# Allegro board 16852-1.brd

Outline 292.8 x 129.5 mm; copper layers: TOP, L2VCC, L3, L4, L5GND, L6, L7GND, BOTTOM. Coordinates in mm from the lower left corner of the outline.

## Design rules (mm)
net group AUDIO_BEEP_15MIL: nets AUD_PORTA_L_HPMIC1 AUD_PORTA_R_HPMIC1
net group CL_CLK: nets CL_CLK CL_CLK_R
net group CL_DATA: nets CL_DATA CL_DATA_R
net group CL_RST#: nets CL_RST# CL_RST#_R
net group CLK_PCIE_WWAN-DIFF1: nets CLK_PCIE_N5_WWAN# CLK_PCIE_P5_WWAN
net group DDPB_CTRL_HDMI-DIFF1: nets CPU_DP1_CTRL_CLK CPU_DP1_CTRL_DATA
net group DDPB_CTRL_HDMI_C-DIFF1: nets DDC_CLK_HDMI DDC_DATA_HDMI
net group DDPC_CTRL_HDMI-DIFF1: nets CPU_DP2_CTRL_CLK CPU_DP2_CTRL_DATA
net group DDR4_A_BA_40-MW: nets M_A_BA0 M_A_BA1
net group DDR4_A_BG_40-MW: nets M_A_BG0 M_A_BG1
net group DDR4_A_ODT10-MW: nets M_A_DIMA_ODT0 M_A_DIMA_ODT1
net group DDR4_B_BA_40-MW: nets M_B_BA0 M_B_BA1
net group DDR4_B_BG_40-MW: nets M_B_BG0 M_B_BG1
net group DDR4_B_ODT10-MW: nets M_B_DIMB_ODT0 M_B_DIMB_ODT1
net group DMIC_DA_CLK-DIFF1: nets DMIC_CLK_R DMIC_DATA_R
net group DMIC_DA_CLK_C-DIFF1: nets DMIC_CLK_EDP DMIC_DATA_EDP
net group DMIC_DA_CLK_R-DIFF1: nets DMIC_CLK DMIC_DATA
net group EDP_AUX_CON_N: nets EDP_AUX_CON_N EDP_AUX_CPU_N
net group EDP_AUX_CON_P: nets EDP_AUX_CON_P EDP_AUX_CPU_P
net group EDP_TX_CON_N0: nets EDP_TX_CON_N0 EDP_TX_CPU_N0
net group EDP_TX_CON_N1: nets EDP_TX_CON_N1 EDP_TX_CPU_N1
net group EDP_TX_CON_P0: nets EDP_TX_CON_P0 EDP_TX_CPU_P0
net group EDP_TX_CON_P1: nets EDP_TX_CON_P1 EDP_TX_CPU_P1
net group GPU_THERMAL-DIFF1: nets GPU_DMINUS GPU_DPLUS
net group HDMI_CLK: nets HDMI_CLK_R HDMI_CLK_R_C
net group HDMI_CLK#: nets HDMI_CLK#_R HDMI_CLK#_R_C
net group HDMI_DATA0: nets HDMI_DATA0_R HDMI_DATA0_R_C
net group HDMI_DATA0#: nets HDMI_DATA0#_R HDMI_DATA0#_R_C
net group HDMI_DATA1: nets HDMI_DATA1_R HDMI_DATA1_R_C
net group HDMI_DATA1#: nets HDMI_DATA1#_R HDMI_DATA1#_R_C
net group HDMI_DATA2: nets HDMI_DATA2_R HDMI_DATA2_R_C
net group HDMI_DATA2#: nets HDMI_DATA2#_R HDMI_DATA2#_R_C
net group I2C0_TCH_PAD-DIFF1: nets I2C0_SCL_TCH_PAD I2C0_SDA_TCH_PAD
net group ICSP-DIFF1: nets ICSP_CLOCK ICSP_DATA
net group ICSP_C-DIFF1: nets ICSP_CLK_R ICSP_DATA_R
net group ISH_I2C0-DIFF1: nets I2C0_SCL I2C0_SDA
net group ISH_I2C1-DIFF1: nets I2C1_SCL I2C1_SDA
net group M_A_CLK0-DIFF1: nets M_A_CLK0 M_A_CLK#0
net group M_A_CLK1-DIFF1: nets M_A_CLK1 M_A_CLK#1
net group M_A_DQS0-DIFF1: nets M_A_DQS_DN0 M_A_DQS_DP0
net group M_A_DQS1-DIFF1: nets M_A_DQS_DN1 M_A_DQS_DP1
net group M_A_DQS2-DIFF1: nets M_A_DQS_DN2 M_A_DQS_DP2
net group M_A_DQS3-DIFF1: nets M_A_DQS_DN3 M_A_DQS_DP3
net group M_A_DQS4-DIFF1: nets M_A_DQS_DN4 M_A_DQS_DP4
net group M_A_DQS5-DIFF1: nets M_A_DQS_DN5 M_A_DQS_DP5
net group M_A_DQS6-DIFF1: nets M_A_DQS_DN6 M_A_DQS_DP6
net group M_A_DQS7-DIFF1: nets M_A_DQS_DN7 M_A_DQS_DP7
net group M_B_CLK0-DIFF186: nets M_B_CLK0 M_B_CLK#0
net group M_B_CLK1-DIFF187: nets M_B_CLK1 M_B_CLK#1
net group M_B_DQS0-DIFF188: nets M_B_DQS_DN0 M_B_DQS_DP0
net group M_B_DQS1-DIFF188: nets M_B_DQS_DN1 M_B_DQS_DP1
net group M_B_DQS2-DIFF188: nets M_B_DQS_DN2 M_B_DQS_DP2
net group M_B_DQS3-DIFF188: nets M_B_DQS_DN3 M_B_DQS_DP3
net group M_B_DQS4-DIFF188: nets M_B_DQS_DN4 M_B_DQS_DP4
net group M_B_DQS5-DIFF188: nets M_B_DQS_DN5 M_B_DQS_DP5
net group M_B_DQS6-DIFF188: nets M_B_DQS_DN6 M_B_DQS_DP6
net group M_B_DQS7-DIFF188: nets M_B_DQS_DN7 M_B_DQS_DP7
net group PBAT_PRES#: nets PBAT_PRES1# PBAT_PRES#
net group PBAT_SMBCLK1: nets PBAT_SMBCLK1 SMBCLK1
net group PBAT_SMBDAT1: nets PBAT_SMBDAT1 SMBDA1
net group PCH_DPC_0-DIFF1: nets PCH_DPC_N0 PCH_DPC_P0
net group PCH_DPC_1-DIFF1: nets PCH_DPC_N1 PCH_DPC_P1
net group PCH_DPC_AUX-DIFF: nets PCH_DPC_AUXN PCH_DPC_AUXP
net group PCI_CLK_LPC0: nets PCI_CLK_LPC0 PCI_CLK_LPC1_B
net group PCIE_CLK_XDP_N: nets PCIE_CLK_XDP_N PEG_CLK_XDP#
net group PCIE_CLK_XDP_P: nets PCIE_CLK_XDP_P PEG_CLK_XDP
net group PCIE_RCOMP-DIFF: nets PCIE_RCOMPN PCIE_RCOMPP
net group PCIE_RX_CON_N5: nets PCIE_RX_CON_N5 PCIE_RX_CPU_N5
net group PCIE_RX_CON_P5: nets PCIE_RX_CON_P5 PCIE_RX_CPU_P5
net group PCIE_RX_CPU6-DIFF192: nets PCIE_RX_CPU_N6 PCIE_RX_CPU_P6
net group PCIE_TX_CON_N5: nets PCIE_TX_CON_N5 PCIE_TX_CPU_N5
net group PCIE_TX_CON_N6: nets PCIE_TX_CON_N6 PCIE_TX_CPU_N6
net group PCIE_TX_CON_P5: nets PCIE_TX_CON_P5 PCIE_TX_CPU_P5
net group PCIE_TX_CON_P6: nets PCIE_TX_CON_P6 PCIE_TX_CPU_P6
net group PEG_CLK_CPU1-DIFF221: nets PEG_CLK1_CPU PEG_CLK1_CPU#
net group PEG_CLK_CPU2-DIFF198: nets PEG_CLK2_CPU PEG_CLK2_CPU#
net group PEG_RX_CPU_N0: nets PEG_RX_CPU_N0 PEG_RX_GPU_N0
net group PEG_RX_CPU_N1: nets PEG_RX_CPU_N1 PEG_RX_GPU_N1
net group PEG_RX_CPU_N2: nets PEG_RX_CPU_N2 PEG_RX_GPU_N2
net group PEG_RX_CPU_N3: nets PEG_RX_CPU_N3 PEG_RX_GPU_N3
net group PEG_RX_CPU_P0: nets PEG_RX_CPU_P0 PEG_RX_GPU_P0
net group PEG_RX_CPU_P1: nets PEG_RX_CPU_P1 PEG_RX_GPU_P1
net group PEG_RX_CPU_P2: nets PEG_RX_CPU_P2 PEG_RX_GPU_P2
net group PEG_RX_CPU_P3: nets PEG_RX_CPU_P3 PEG_RX_GPU_P3
net group PEG_TX_CPU_N0: nets PEG_TX_CPU_N0 PEG_TX_GPU_N0
net group PEG_TX_CPU_N1: nets PEG_TX_CPU_N1 PEG_TX_GPU_N1
net group PEG_TX_CPU_N2: nets PEG_TX_CPU_N2 PEG_TX_GPU_N2
net group PEG_TX_CPU_N3: nets PEG_TX_CPU_N3 PEG_TX_GPU_N3
net group PEG_TX_CPU_P0: nets PEG_TX_CPU_P0 PEG_TX_GPU_P0
net group PEG_TX_CPU_P1: nets PEG_TX_CPU_P1 PEG_TX_GPU_P1
net group PEG_TX_CPU_P2: nets PEG_TX_CPU_P2 PEG_TX_GPU_P2
net group PEG_TX_CPU_P3: nets PEG_TX_CPU_P3 PEG_TX_GPU_P3
net group POWER_240M_POWER: nets 1D5V_VGA_S0 PWR_1D5V
net group POWER_280M_19V: nets PWR_DCBATOUT_1D35V PWR_DCBATOUT_VDDQ
net group PWR_DISB: nets PWR_VCCGT_DISB#_A PWR_VCORE_DISB#
net group PWR_V_F: nets DCBATOUT_VCCGT DCBATOUT_VCORE
net group PWR_VCCGT: nets PWR_VCCGT_CSCOMP PWR_VCCGT_ILIM_R
net group PWR_VCORE_VSN: nets PWR_VCORE_VSN PWR_VCORE_VSN_R
net group SENSE_CHG_AC-DIFF: nets PWR_CHG_ACN PWR_CHG_ACP
net group SENSE_CHG_SR-DIFF: nets PWR_CHG_SRN PWR_CHG_SRP
net group SIGNAL_V_F_8_OHM-MW: nets CFG3 XDP_DBRESET#
net group SIGNAL_V_F_18_OHM-MW: nets H_PECI PECI_EC
net group SMBUS0_PCH-DIFF1: nets SML0_SMBCLK SML0_SMBDATA
net group SMBUS1_GPU-DIFF1: nets SMB_CLK_VGA SMB_DATA_VGA
net group SMBUS1_GPU_T8-DIFF1: nets SMB_CLK_VGA_GPUT8 SMB_DATA_VGA_GPUT8
net group SMBUS_XDP-DIFF1: nets XDP_SMBCLK XDP_SMBDAT
net group SPI_WP_CPU: nets SPI_WP_ROM SPI_WP_ROM_R
net group THERM_7718E-DIFF1: nets NCT7718_DXN NCT7718_DXP
net group USB3_PRX_CTX_C1-DIFF1: nets USB3_PRX_CTX_N1_C USB3_PRX_CTX_P1_C
net group USB3_PRX_CTX_C3-DIFF1: nets USB3_PRX_CTX_N3_C USB3_PRX_CTX_P3_C
net group USB3_PTX_CRX_C1-DIFF1: nets USB3_PTX_CRX_N1_C USB3_PTX_CRX_P1_C
net group USB3_PTX_CRX_C2-DIFF1: nets USB3_TXN3_R USB3_TXP3_R
net group USB3_PTX_CRX_C3-DIFF1: nets USB3_PTX_CRX_N3_C USB3_PTX_CRX_P3_C
net group USB3_PTX_CRX_R3-DIFF1: nets USB3_PTX_CRX_N3_R USB3_PTX_CRX_P3_R
net group USB30_RX_CPU1-DIFF1: nets USB30_RX_CPU_N1 USB30_RX_CPU_P1
net group USB30_RX_CPU3-DIFF1: nets USB30_RX_CPU_N3 USB30_RX_CPU_P3
net group USB30_TX_CPU2-DIFF1: nets USB30_TX_CPU_N2 USB30_TX_CPU_P2
net group USB30_TX_CPU3-DIFF1: nets USB30_TX_CPU_N3 USB30_TX_CPU_P3
net group USB_CON6-DIFF6: nets USB_CON_PN6 USB_CON_PP6
net group USB_CPU3-DIFF3: nets USB_CPU_PN3 USB_CPU_PP3
net group USB_CPU6-DIFF6: nets USB_CPU_PN6 USB_CPU_PP6
net group USB_CPU7-DIFF7: nets USB_CPU_PN7 USB_CPU_PP7
net group USB_CPU_PN0: nets USB_PN0_C USB_PN0_R
net group USB_CPU_PN2: nets USB_CPU_PN2 USB_PN2_C
net group USB_CPU_PN5: nets USB_CPU_PN5 USB_PN5_C
net group USB_CPU_PP0: nets USB_PP0_C USB_PP0_R
net group USB_CPU_PP2: nets USB_CPU_PP2 USB_PP2_C
net group USB_CPU_PP5: nets USB_CPU_PP5 USB_PP5_C
net group USB_PN3_PP3_C-DIFF1: nets USB_PN3_C USB_PP3_C
net group USB_WLAN-DIFF219: nets USB_CON_PN7 USB_CON_PP7
net group VRAM_CLK0-DIFF1: nets CLKA0 CLKA0#
net group VRAM_CLK1-DIFF1: nets CLKA1 CLKA1#
net group VRAM_CSA: nets CSA0#_0 CSA1#_0
net group VRAM_QS0-DIFF1: nets QSAN_0 QSAP_0
net group VRAM_QS1-DIFF1: nets QSAN_1 QSAP_1
net group VRAM_QS2-DIFF1: nets QSAN_2 QSAP_2
net group VRAM_QS3-DIFF1: nets QSAN_3 QSAP_3
net group VRAM_QS4-DIFF1: nets QSAN_4 QSAP_4
net group VRAM_QS5-DIFF1: nets QSAN_5 QSAP_5
net group VRAM_QS6-DIFF1: nets QSAN_6 QSAP_6
net group VRAM_QS7-DIFF1: nets QSAN_7 QSAP_7
net group XTAL24_IN: nets XTAL24_IN XTAL24_IN_R
net group AUDIO_12MIL: nets AUD_VREF CBP CPVDD CPVEE LDO1_CAP LDO2_CAP V3D3_STB
net group AUDIO_BEEP1_40MIL: nets AUD_SPK_L+ AUD_SPK_L+_C AUD_SPK_L- AUD_SPK_L-_C AUD_SPK_R+ AUD_SPK_R+_C AUD_SPK_R- AUD_SPK_R-_C
net group AUDIO_BEEP_10MIL: nets AUD_HP1_JACK_L AUD_HP1_JACK_L1 AUD_HP1_JACK_R AUD_HP1_JACK_R1 AUD_PC_BEEP_3246 AUD_PC_BEEP_C AUD_PC_BEEP_R AUD_SENSE AUD_SENSE_A BEEP CBN HDA_SPKR_R JACK_PLUG JACK_PLUG_DET KBC_BEEP_R LINE1-L_C LINE1-L_R LINE1_L LINE1_R LINE1_VREFO_L LINE1_VREFO_R MIC2_VREFO SPKR
net group AUDIO_DIGITAL_50-MW: nets HDA_RST#
net group AUDIO_SLEEVE_40MIL: nets RING2 RING2_HPMIC1 SLEEVE SLEEVE_HPMIC1
net group CFG_50-MW: nets CFG0 CFG1 CFG2 CFG4 CFG5 CFG6 CFG7 CFG8 CFG9 CFG10 CFG11 CFG12 CFG13 CFG14 CFG15 CFG16 CFG17 CFG18 CFG19
net group CLK_50-MW: nets CLK_PCI_LPC CLK_PCI_LPC_MEC CLK_PCI_LPC_R CLKTESTA CLKTESTA_C CLKTESTB CLKTESTB_C PWR_CHG_PROCHOT# SUS_CLK SUS_CLK_WLAN_WWAN SUSCLK_NGFF_C SUSCLK_R SUSCLK_WLAN WLAN_CLKREQ_WLAN#
net group CLK_ITE8010: nets CLK_ITE8010 SMB_CLK_VGA_R SMBCLK2 SML1_SMBCLK THM_SML1_CLK
net group COMP_20MIL: nets CFG_RCOMP CPU_POPIRCOMP CSI2_COMP EDP_COMP EDRAM_OPIO_RCOMP EMMC_RCOMP EOPIO_RCOMP PCH_POPIRCOMP SD_RCOMP USBCOMP XCLK_BIASREF
net group CPU_50-MW: nets CMP_VOUT1 H_PROCHOT# H_PROCHOT#_EC H_PROCHOT#_R H_PROCHOT#_R_R PQ4405_3
net group CPU_50_12MIL: nets H_VCCST_PWRGD H_VCCST_PWRGD_R PCH_THERMTRIP
net group DAT_ITE8010: nets DAT_ITE8010 SMB_DATA_VGA_R SMBDA2 SML1_SMBDATA THM_SML1_DATA
net group DDR4_A_CKE_40-MW: nets M_A_CKE0 M_A_CKE1 M_A_CS#0 M_A_CS#1
net group DDR4_A_CMD_40-MW: nets M_A_A0 M_A_A1 M_A_A2 M_A_A3 M_A_A4 M_A_A5 M_A_A6 M_A_A7 M_A_A8 M_A_A9 M_A_A10 M_A_A11 M_A_A12 M_A_A13 M_A_A14 M_A_A15 M_A_A16 M_A_ACT_N M_A_ALERT_N M_A_PARITY M_B_ALERT_N
net group DDR4_A_DATA_00_50-MW: nets M_A_DQ0 M_A_DQ1 M_A_DQ2 M_A_DQ3 M_A_DQ4 M_A_DQ5 M_A_DQ6 M_A_DQ7
net group DDR4_A_DATA_01_50-MW: nets M_A_DQ8 M_A_DQ9 M_A_DQ10 M_A_DQ11 M_A_DQ12 M_A_DQ13 M_A_DQ14 M_A_DQ15
net group DDR4_A_DATA_02_50-MW: nets M_A_DQ16 M_A_DQ17 M_A_DQ18 M_A_DQ19 M_A_DQ20 M_A_DQ21 M_A_DQ22 M_A_DQ23
net group DDR4_A_DATA_03_50-MW: nets M_A_DQ24 M_A_DQ25 M_A_DQ26 M_A_DQ27 M_A_DQ28 M_A_DQ29 M_A_DQ30 M_A_DQ31
net group DDR4_A_DATA_04_50-MW: nets M_A_DQ32 M_A_DQ33 M_A_DQ34 M_A_DQ35 M_A_DQ36 M_A_DQ37 M_A_DQ38 M_A_DQ39
net group DDR4_A_DATA_05_50-MW: nets M_A_DQ40 M_A_DQ41 M_A_DQ42 M_A_DQ43 M_A_DQ44 M_A_DQ45 M_A_DQ46 M_A_DQ47
net group DDR4_A_DATA_06_50-MW: nets M_A_DQ48 M_A_DQ49 M_A_DQ50 M_A_DQ51 M_A_DQ52 M_A_DQ53 M_A_DQ54 M_A_DQ55
net group DDR4_A_DATA_07_50-MW: nets M_A_DQ56 M_A_DQ57 M_A_DQ58 M_A_DQ59 M_A_DQ60 M_A_DQ61 M_A_DQ62 M_A_DQ63
net group DDR4_B_CKE_40-MW: nets M_B_CKE0 M_B_CKE1 M_B_CS#0 M_B_CS#1
net group DDR4_B_CMD_40-MW: nets M_B_A0 M_B_A1 M_B_A2 M_B_A3 M_B_A4 M_B_A5 M_B_A6 M_B_A7 M_B_A8 M_B_A9 M_B_A10 M_B_A11 M_B_A12 M_B_A13 M_B_A14 M_B_A15 M_B_A16 M_B_ACT_N M_B_PARITY
net group DDR4_B_DATA_00_50-MW: nets M_B_DQ0 M_B_DQ1 M_B_DQ2 M_B_DQ3 M_B_DQ4 M_B_DQ5 M_B_DQ6 M_B_DQ7
net group DDR4_B_DATA_01_50-MW: nets M_B_DQ8 M_B_DQ9 M_B_DQ10 M_B_DQ11 M_B_DQ12 M_B_DQ13 M_B_DQ14 M_B_DQ15
net group DDR4_B_DATA_02_50-MW: nets M_B_DQ16 M_B_DQ17 M_B_DQ18 M_B_DQ19 M_B_DQ20 M_B_DQ21 M_B_DQ22 M_B_DQ23
net group DDR4_B_DATA_03_50-MW: nets M_B_DQ24 M_B_DQ25 M_B_DQ26 M_B_DQ27 M_B_DQ28 M_B_DQ29 M_B_DQ30 M_B_DQ31
net group DDR4_B_DATA_04_50-MW: nets M_B_DQ32 M_B_DQ33 M_B_DQ34 M_B_DQ35 M_B_DQ36 M_B_DQ37 M_B_DQ38 M_B_DQ39
net group DDR4_B_DATA_05_50-MW: nets M_B_DQ40 M_B_DQ41 M_B_DQ42 M_B_DQ43 M_B_DQ44 M_B_DQ45 M_B_DQ46 M_B_DQ47
net group DDR4_B_DATA_06_50-MW: nets M_B_DQ48 M_B_DQ49 M_B_DQ50 M_B_DQ51 M_B_DQ52 M_B_DQ53 M_B_DQ54 M_B_DQ55
net group DDR4_B_DATA_07_50-MW: nets M_B_DQ56 M_B_DQ57 M_B_DQ58 M_B_DQ59 M_B_DQ60 M_B_DQ61 M_B_DQ62 M_B_DQ63
net group DDR4_VREF_40: nets M_VREF_CA_DIMMA M_VREF_CA_DIMMB V_SM_VREF_CNTA V_SM_VREF_CNTB
net group EC_SPI_CLK: nets EC_SPI_CLK SPI1_CLK_ROM_R SPI_CLK_CPU SPI_CLK_ROM SPI_CLK_ROM_R SPI_CLK_ROM_TPM1 SPI_CLK_ROM_TPM2
net group EC_SPI_CS0#: nets EC_SPI_CS0# SPI_CS_CPU_N0 SPI_CS_ROM_N0
net group EC_SPI_MISO: nets EC_SPI_MISO SPI1_SO_ROM_R SPI_SO_CPU SPI_SO_ROM SPI_SO_ROM_R SPI_SO_ROM_TPM1 SPI_SO_ROM_TPM2
net group EC_SPI_MOSI: nets EC_SPI_MOSI SPI1_SI_ROM_R SPI_SI_CPU SPI_SI_ROM SPI_SI_ROM_R SPI_SI_ROM_TPM1 SPI_SI_ROM_TPM2
net group FAN_TACH: nets FAN1_TACH FAN_TACH1 FAN_TACH1_C
net group FBA_VREF: nets FBA_VREF_0 FBA_VREF_1 MVREFDA MVREFSA
net group GND: nets 81208_AGND CHG_AGND EC_AGND JGND MIC_GND
net group H_CPU_SVIDALRT#: nets H_CPU_SVIDALRT# PWR_VCORE_ALERT# VR_SVID_ALERT#
net group H_CPU_SVIDCLK: nets H_CPU_SVIDCLK PWR_VCORE_SCLK VR_SVID_CLK
net group H_CPU_SVIDDAT: nets H_CPU_SVIDDAT PWR_VCORE_SDIO VR_SVID_DATA
net group HDA_BITCLK: nets HDA_BITCLK_CODEC_R
net group HDA_CODEC_SDIN0: nets HDA_SDIN0
net group HDA_CODEC_SDOUT: nets HDA_SDOUT_CODEC_R
net group JTAG-MW: nets PCH_JTAG_TCK PCH_JTAG_TDI PCH_JTAG_TDO PCH_JTAG_TMS
net group KBC: nets KSI0 KSI1 KSI2 KSI3 KSI4 KSI5 KSI6 KSI7 KSO0 KSO1 KSO2 KSO3 KSO4 KSO5 KSO6 KSO7 KSO8 KSO9 KSO10 KSO11 KSO12 KSO13 KSO14 KSO15 KSO16
net group LCD_BKLT: nets BKLT_CTRL EDP_BKLT_CTRL L_BKLT_CTRL LCD_BRIGHTNESS MASK_BASE_LEDS#
net group LED: nets BAT1_LED# BAT2_LED# BATT_WHITE_LED# BATT_WHITE_LED#_M BATT_WHITE_LED_R# CAP_LED# CAP_LED#_S CAP_LED_R# CHG_AMBER_LED# CHG_AMBER_LED#_M CHG_AMBER_LED_R# NGFF_WAKE# PWR_LED# PWR_LED#_B PWR_LED#_S SATA#/BATT_LED_MUXCTL SATA_LED#_R
net group LED_20MIL: nets AMBER_LED_BAT BAT_AMBER BAT_WHITE CAP_LED CAP_LED_Q PWR_LED PWR_LED#_R WHITE_LED_BAT
net group LPC-MW: nets CLKRUN#_R L_CPM_CLK L_CPM_CLK_R LPC_FRAME#_DEBUG LPC_LAD0 LPC_LAD0_C LPC_LAD0_CPM LPC_LAD0_R LPC_LAD1 LPC_LAD1_C LPC_LAD1_CPM LPC_LAD1_R LPC_LAD2 LPC_LAD2_C LPC_LAD2_CPM LPC_LAD2_R LPC_LAD3 LPC_LAD3_C LPC_LAD3_CPM LPC_LAD3_R LPC_LFRAME# LPC_LFRAME#_CPM LPC_LFRAME#_R PCI_CLK_LPC1 PCI_CLK_LPC1_B_R SERIRQ
net group OTHER_4MIL: nets 3.3V_ALW_1 3.3V_RUN_VGA_1 +3VLP A5_TP A67_TP A70_TP A_A0 A_A1 A_A2 AC_DIS AC_IN_KBC# AC_PRESENT AD_IA ATI_RST# AUX_EN_WOWL AUX_EN_WOWL_GP0 AUX_EN_WOWL_R AV1_TP AV71_TP B71_TP BA1_TP BA2_TP BA71_TP BB67_TP BB70_TP BLON_OUT_C BLUETOOTH_EN BLUETOOTH_EN_NGFF BOARD_ID BOARD_ID2 CLKREQ_PCIE#1 CLKREQ_PCIE#2 CLKREQ_PCIE#3 CLKREQ_PCIE#4 CLKREQ_PCIE#5 CLKREQ_PEG#0 CLKRUN# CPU_DP1_HPD CPU_DP2_HPD CPU_DP2_HPD1 DBC_EN_R DBC_PANEL_EN DDPD_CTRLDATA DRAM_RST DRAM_RST_R DRAM_RST_VGA1 DVSS E51_RX1 E51_RX2 E51_TX1 E51_TXD_R E71_TP EC_MUTE# EC_WAKE# EDP_DISP_UTIL EDP_HPD EDP_HPD_CONN FALL_INT2 FFS_INT2 FFS_INT2_Q GPD2/LAN_WAKE# GPIO16_VGA GPIO_8_ROMSO GPIO_9_ROMSI GPIO_10_ROMSCK GPIO_17_THERMAL_INT GPIO_19_CTF GPIO_22_ROMCS# GPP_B2/VRALERT# GPP_B4/CPU_GP3 GPP_B18/GSPI0_MOSI GPP_B23/SML1ALERT# GPP_C2/SMBALERT# GPP_C5/SML0ALERT# GPP_D4/FLASHTRIG GPP_E0/SATAXPCIE0/SATAGP0 GPP_E2/SATAXPCIE2/SATAGP2 GPP_E3/CPU_GP0 GPU_ALERT# GPU_DPRSLP GPU_DPRSLP_R H_CATERR# H_VID3 H_VID4 HDD_DEVSLP_R HDD_DEW1 HDD_DEW2 HDD_FALL_INT HDMI_HPD_B HDMI_HPD_E HOST_DEBUG_TX HPD_HDMI_CON I_ADP I_SYS ICSP_CLR ICSP_CLR_R ILIM_HI ILIM_SEL INT#_ITE8010 INT_TP# IR_CAMERA_DET# IR_CAMERA_DET#_R JDREF JET_SVC JET_SVD JTAG_TCK_VGA JTAG_TDI_VGA JTAG_TDO_VGA JTAG_TMS_VGA JTAG_TRST#_VGA KB_LED_BL_DET KB_LED_DET_C KBC_PWRBTN# L_BKLT_EN L_BKLT_EN_EC LAN_DISABLE# LCD_TST LCD_TST_C LCD_VCC_TEST_EN LCDVDD_EN LED0 LED1 LED2 LID_CL_SIO# ME_FWP_CPU ME_FWP_EC MEM_CALRP0 MESO_SVC MESO_SVD MESO_SVT MESO_U1 MESO_U3 MESW1_B MLPS_EN# MODEL_ID MSM# NC#AA3 NC_R NC_VSYNC NCT7718_ALERT# NGFF_CONFIG_0 NGFF_CONFIG_1 NGFF_CONFIG_2 NGFF_CONFIG_3 NGFF_DEVSLP1 NGFF_MSATA_DEVSLP NGFF_PCIE#_SATA P_SYS PANEL_BKEN_EC PANEL_SIZE_ID PANEL_SIZE_ID_CONN PCH_ALW_ON PCH_BATLOW# PCH_PLTRST#_EC PCH_WAKE# PD4403_A PD4403_K PD# PIRQA# PLL_ANALOG_IN PLT_RST_NGFF# POWER_SW_IN# PQ4405_2 PQ4405_5 PQ4405_6 PQ4408_C PQ4408_E PROC_SELECT# PROJECT_ID2 PS_0 PS_1 PS_2 PS_3 PS_ID_R1 PSYS PWR_CHG_ACOK PWRGOOD_TEST PX_EN Q4009_G RESET_OUT# RTC_DET# SA0_CHA_DIM0 SA0_CHB_DIM0 SA1_CHA_DIM0 SA1_CHB_DIM0 SA2_CHA_DIM0 SA2_CHB_DIM0 SATA_DE1_HDD SATA_DE2_HDD SATA_EQ1_HDD SATA_EQ2_HDD SERIRQ_TPM SIO_EXT_SCI#_R SIO_EXT_SMI# SIO_EXT_SMI#_R SIO_EXT_WAKE# SIO_PWRBTN# SIO_SLP_A# SIO_SLP_S5# SIO_SLP_SUS# SKTOCC# SM_INTRUDER# SPI_IRQ# TESTEN TOUCHPAD_INTR# TP_PMODE_XDP_RST_R_N TP_RESET TP_RS USB_OC1# USB_OC2# USB_UART_SEL_D9 VCC_OPC_1P8_H63 VCI_IN1# VGA_RST# VR_RDY VRAM_ID1 VSS_MECH1 VSS_MECH2 VSS_MECH3 VSSRHA WIFI_RF_EN WLAN_DISABLE#1 XO_IN2 ZVM#
net group PERN0/SATA_B-: nets SATA_RN1/PERN6_L0
net group PERP0/SATA_B+: nets SATA_RP1/PERP6_L0
net group PETN0/SATA_A-: nets SATA_TN1/PETN6_L0
net group PETP0/SATA_A+: nets SATA_TP1/PETP6_L0
net group PLATFORM: nets 0D95V_VGA_EN 0D95V_VGA_EN_R 0D95V_VGA_S0_PG 1D0V_S5_PWRGD 1D8V_EN# 1D8V_EN_R# 1D8V_S5_PWROK 1D8V_VGA_EN 1D8V_VGA_EN# 1D8V_VGA_EN_R# 3.3V_WLAN_EN 3.3V_WLAN_ENABLE 3.3V_WLAN_ENABLE# 3.3V_WWAN_ENABLE 3.3V_WWAN_ENABLE# 3V5V_S0_ON 3V_5V_POK 3V_5V_POK# 3V_5V_POK_C ALWON BLON_OUT CLK_LAN_REQ4#_R CLKA0_CLKA0# CLKA1_CLKA1# DGPU_PWROK_KBC DS3_PWRCTL DSW1 EDP_VDD_EN EXT_PWR_GATE# FIVR_EN_R GPD11/LANPHYPC GPIO_5_AC_BATT H_CPUPWRGD HDD_DET# HW_GPS_DISABLE2# HW_GPS_DISABLE2#_D KBC_PWRBTN#_C LAN_EN LAN_ENABLE_R_C LAN_RSET LCD_MIC_CBL_DET# LCD_MIC_CBL_DET#_R LOM_CABLE_DETECT# MCARD_WWAN_PWREN ME_SUS_PWR_ACK ME_SUS_PWR_ACK_R PCH_DPWROK PCH_PLTRST# PCH_RSMRST# PCIE_CALR_RX PCIE_CALR_TX PCIE_LAN_WAKE# PCIE_WAKE# PCIE_WLAN_WAKE# PCIE_WLAN_WAKE#_R PLT_RST#_DEBUG PLT_RST#_LAN PM_LAN_ENABLE PM_LAN_ENABLE_C PM_PCH_PWROK PM_RSMRST# PM_RSMRST#_M PM_RSMRST#_R PM_RSMRST_PWRGD_XDP PS_S3CNTRL PTP_DIS# PTP_INT#_EC PWR_1D0V_EN PWR_1D0V_PG PWR_1D8V_EN PWR_1D8V_POK PWR_1D35V_EN PWR_1D35V_PG PWR_2D5V_PG PWR_3D3V_EN PWR_VCORE_EN Q502_G Q9102.G RSMRST_PWRGD# RTC_RST# RTCRST_ON RUNPWROK SD_READ_MODE# SIO_SLP_S4# SLP_LAN# SM_DRAMRST# SM_PGCNTL SM_PGCNTL_R SRTC_RST# SUS_STAT#/LPCPD# SUSACK# SUSACK#_R TP_EN# TP_LOCK# TP_ON#_GATE TPM_GPIO0 TPM_GPIO2 TPM_GPIO4 TS#_DIMM0_1 TS#_DIMM1_1 UIM_DET UIM_DET# UIM_DET#_G UIM_DET_D UIM_RESET UIM_RESET_R USB2_ID USB2_VBUSSENSE USB_CHG_EN USB_EN# USB_PWR_EN# USBCHARGER_CB0 VCCSTG_EN VCCSTG_EN_R VCCSTU_EN VCCSTU_EN_R VPP_EN_R WWAN_PERST# WWAN_PWR_EN_D WWAN_PWR_OFF# WWAN_RADIO_DIS# WWAN_RADIO_DIS#_D WWAN_RESET# XO_IN
net group POWER_10M: nets 1.8V_RUN_FB 3V5V_CT1 3V5V_CT2 +V1.00A_XDP +V1.00U_CPU +VCCAMPHYPLL_1P0 +VCCAMPHYPLL_1P0_L +VCCAPLL_1P0 +VCCDSW_1P0 +VCCFUSEPRG +VCCPAZIO +VCCPDSW_3P3 +VCCPRTC_3P3 +VCCST_CPU +VCCSTG +VDDQ_CPU_CLK ACAV_IN ACOK_IN BOOST_MON FAN1_DAC FAN1_DAC_1 FBA_ZQ0 FBA_ZQ1 FBA_ZQ2 FBA_ZQ3 FP_PWR I_BATT LDO3_CAP MIC_CAP PWR_1D0V_PFM PWR_1D0V_SS PWR_1D0V_TON PWR_1D0V_VFB PWR_1D0V_VFB_A PWR_1D35V_FB PWR_1D35V_FB_A PWR_1D35V_ILMT PWR_3D3V_FB PWR_5V_EN PWR_5V_FB PWR_5V_FB_A PWR_CHG_1 PWR_CHG_BATPRES# PWR_CHG_BATSRC PWR_CHG_STAT# PWR_VCCGT_COMP PWR_VCCGT_COMP_R PWR_VCCGT_CSNA PWR_VCCGT_CSP1 PWR_VCCGT_CSP2 PWR_VCCGT_CSPA PWR_VCCGT_CSREF PWR_VCCGT_CSSUM PWR_VCCGT_DIFFOUT PWR_VCCGT_FB PWR_VCCGT_FB_R PWR_VCCGT_ICCMAX PWR_VCCGT_ILIM PWR_VCCGT_IOUT PWR_VCCGT_NTC PWR_VCCGT_PWMA PWR_VCCGT_TSENSE PWR_VCCGT_VCCA PWR_VCCGT_VSN PWR_VCCGT_VSN_R PWR_VCCGT_VSP PWR_VCCSA_COMP PWR_VCCSA_COMP_R PWR_VCCSA_CSN PWR_VCCSA_CSN_NTC PWR_VCCSA_CSP PWR_VCCSA_CSP1B PWR_VCCSA_ICCMAX PWR_VCCSA_ILIM PWR_VCCSA_IOUT PWR_VCCSA_VSN PWR_VCCSA_VSN_R PWR_VCCSA_VSP PWR_VCCSA_VSP_R PWR_VCCSA_VSP_RC PWR_VCORE_COMP PWR_VCORE_COMP_R PWR_VCORE_CSN PWR_VCORE_CSNNTC PWR_VCORE_CSP PWR_VCORE_CSP_1A PWR_VCORE_DRVON PWR_VCORE_ICCMAX PWR_VCORE_ILIM PWR_VCORE_IOUT PWR_VCORE_NTC PWR_VCORE_ROSC_COREGT PWR_VCORE_ROSC_SAUS PWR_VCORE_TSENSE PWR_VCORE_VCC_R PWR_VCORE_VR_RDY PWR_VCORE_VRHOT# PWR_VCORE_VRMP PWR_VCORE_VSP PWR_VCORE_VSP_R PWR_VCORE_VSP_RC PWR_VDDQ_EN PWR_VDDQ_FB PWR_VDDQ_VCC Q6204_G V0.85A_VID0 VCCRTCEXT
net group POWER_10M_POWER: nets AC_IN#_G AD+_G_1 AD+_G_2 AD_OFF_L AD_OFF_R BT+_1 DC_IN_D DDR_VREF_S3 DPLL_PVDD DPLL_VDDC EN/DEM_VGA MPV18 PQ3809_D PQ8206_3 PU8201_36 PU8201_39 PWR_0D6V_S3EN PWR_0D6V_S5EN PWR_0D95V_FB PWR_1D35V_VCC PWR_3D3V_CS PWR_3D3V_VREG PWR_5V_CS PWR_CHG_ACDET PWR_CHG_CMPIN PWR_CHG_CMPOUT PWR_CHG_IADP PWR_CHG_IDCHG PWR_CHG_ILIM PWR_CHG_PMON PWR_CHG_REGN PWR_CHG_SCL PWR_CHG_SDA PWR_CHG_SRN_1 PWR_CHG_SRP_1 PWR_VCCGT_GL1 PWR_VCCSA_PWM PWR_VCORE_ADDR_BOOT PWR_VCORE_GL PWR_VCORE_PWM PWR_VDDQ_ILMT PWR_VDDQ_PG PWR_VGA_CORE_COMP PWR_VGA_CORE_COMP_1 PWR_VGA_CORE_EN_R# PWR_VGA_CORE_ENABLE PWR_VGA_CORE_FB PWR_VGA_CORE_FB2_R PWR_VGA_CORE_FB_R PWR_VGA_CORE_IMON PWR_VGA_CORE_IMON_NB PWR_VGA_CORE_ISEN1 PWR_VGA_CORE_ISEN2 PWR_VGA_CORE_ISUMN PWR_VGA_CORE_ISUMP PWR_VGA_CORE_NTC PWR_VGA_CORE_NTC_NB PWR_VGA_CORE_PGOOD PWR_VGA_CORE_PH1 PWR_VGA_CORE_PH2 PWR_VGA_CORE_PWROK PWR_VGA_CORE_RTN PWR_VGA_CORE_SVC PWR_VGA_CORE_SVD PWR_VGA_CORE_SVT PWR_VGA_CORE_VDD PWR_VGA_CORE_VDDIO PWR_VGA_CORE_VO1 PWR_VGA_CORE_VO2 PWR_VGA_CORE_VR_HOT# PWR_VGA_CORE_VSEN PWR_VGA_CORE_VSUM- SPV10 SPV18 TOPAZ_OCP VGA_SVC VGA_SVD VGA_SVT VGA_VDD_RUN_FB_H VGA_VDD_RUN_FB_L VGA_VSUM-_1 VSS_AY71
net group POWER_10M_POWER_20MIL: nets PWR_3D3V_FB_A PWR_3D3V_FB_B PWR_VDDQ_FB_A
net group POWER_15M: nets 3D3V_TP_S5_R Q6205_Q TP_VDD
net group POWER_15M_POWER: nets PWR_5V_VO
net group POWER_20M: nets 1D8V_S0 3D3V_AUX_KBC_33 3D3V_AUX_KBC_R 3D3V_AUX_S5 3D3V_RUN_FFS 3D3V_S5_KBC 5V_AUX_S5 +3V_1D8V_AVDD +5V_AVDD +RTC_VCC +V_VREF_PATH1 +V_VREF_PATH2 +VCCCLK2 +VCCCLK4 +VCCCLK5 EC_VTT ECVBAT MCT0 MCT1 MCT2 MCT3 PS_ID_R PWR_1D0V_BT PWR_1D0V_PH PWR_1D35V_BOOT PWR_1D35V_BOOT_A PWR_1D35V_PH PWR_3D3V_BOOT PWR_3D3V_BOOT_A PWR_5V_BOOT PWR_5V_BOOT_A PWR_CHG_BTST PWR_VCCGT_SNUB_1 RTC_AUX_S5 RTC_PWR SYS_PRES1# TPAN_VDD UIM_PWR UIM_RFU UIM_VPP
net group POWER_20M_POWER: nets +3V_AVDD +5V_KB_BL BKLGT_PWM KB_BL_CTRL# LAN_REGOUT PWR_0D6V_VCNTL PWR_CHG_CMSRC PWR_CHG_VCC PWR_VCCGT_BOOTA PWR_VCCGT_BOOTA_RC PWR_VCCGT_PHASEDA PWR_VCCSA_BST PWR_VCCSA_BST_RC PWR_VCCSA_SNUB PWR_VCORE_BOOT PWR_VCORE_BOOT_RC PWR_VCORE_PHASED PWR_VCORE_SNUB PWR_VCORE_VCC PWR_VDDQ_BOOT PWR_VGA_CORE__BOOT1_1 PWR_VGA_CORE__BOOT2_1 PWR_VGA_CORE_BOOT1 PWR_VGA_CORE_BOOT2 PWR_VGA_SNUB1 PWR_VGA_SNUB2 VDD10
net group POWER_25M: nets 1D8V_VGA_S0 PQ3802_1 PS_ID PS_ID_R2 PSID_DISABLE#_R_C
net group POWER_25M_20MIL: nets 0D6V_PWR PWR_3D3V_HG PWR_3D3V_LG PWR_5V_HG PWR_5V_LG PWR_VDDQ_BOOT_A
net group POWER_30M_POWER: nets PWR_CHG_HIDRV PWR_CHG_LODRV PWR_CHG_PHASE
net group POWER_40M: nets 1D8V_PWR 1D8V_S5 3D3V_CAMERA_S0 3D3V_CPM_Z32H 3D3V_LAN_S5 3D3V_S5_IT8010 3D3V_S5_PCH 3D3V_SPIVCC2 3D3V_TPM 3D3V_TPM_1 +UZ12_TPM DCBATOUT_CAMERA FAN_VCC1 HDMI_PLL_GND LOM_TCT MCT PWR_2D5V TPAN_VDD_F TPM_VDD14 TPM_VDD22 TPM_VSB U4101_OUT VDDREG
net group POWER_40M_19V: nets DCBATOUT_LCD
net group POWER_40M_POWER: nets 5V_HDMI_S0 PWR_0D95V_PHASE PWR_0D95V_PVDD PWR_VCCSA_DRVH PWR_VCCSA_DRVL PWR_VDDQ_PH PWR_VGA_CORE_LGATE1 PWR_VGA_CORE_LGATE2 PWR_VGA_CORE_LGATE_NB PWR_VGA_CORE_PHASE1 PWR_VGA_CORE_PHASE2 PWR_VGA_CORE_UGATE1 PWR_VGA_CORE_UGATE2 PWR_VGA_CORE_UGATE_LX_NB
net group POWER_60M_POWER: nets DCBATOUT_+VCCSA
net group POWER_80M: nets 0D6V_S0 2D5V_S3 3D3V_VGA_S0 5V_HDD_S0 +5V_PVDD LCDVDD LCDVDD_LCD
net group POWER_100M: nets 3D3V_MSATA_S0 PWR_DCBATOUT_1D0V USB30_VCCB USB30_VCCC
net group POWER_120MIL: nets 3D3V_S5_WLAN 3D3V_S5_WWAN +V1.8A_SIP +VCCAPLLEBB_1P0
net group POWER_160M: nets 0D95V_VGA_S0 PWR_0D95V PWR_3D3V PWR_5V USB20_VCCA
net group POWER_160M_POWER: nets PWR_2D5V_FB PWR_3D3V_PH PWR_5V_PH PWR_DCBATOUT_3D3V PWR_DCBATOUT_5V
net group POWER_200M: nets +SDC_IN
net group POWER_240M: nets +V1.00U_CPU_LS
net group POWER_280M_POWER: nets 1D2V_S3 PWR_VCCSA_SW PWR_VDDQ
net group POWER_320M: nets +V3.3A_SIP
net group POWER_320M_POWER: nets +DC_IN +DC_IN_C AC_DIS_M AD+ BT+ CHARGER_SRC PWR_DCBATOUT_VGA_CORE1 PWR_DCBATOUT_VGA_CORE2
net group POWER_320M_POWER_NO_TP: nets PWR_CHG_PHASE_1
net group POWER_400M: nets 1D0V_PWR
net group POWER_1360M_POWER: nets PWR_VCCGT_SWA
net group POWER_1600M: nets PWR_VCORE_SW
net group REF10M: nets VR_CAP
net group SATA_RX_CON_N0: nets SATA_RX_CPU_N0 SATA_RX_CPU_N0_R SATA_RX_R_N0
net group SATA_RX_CON_P0: nets SATA_RX_CPU_P0 SATA_RX_CPU_P0_R SATA_RX_R_P0
net group SATA_TX_CON_N0: nets SATA_TX_CPU_N0 SATA_TX_CPU_N0_R SATA_TX_R_N0
net group SATA_TX_CON_P0: nets SATA_TX_CPU_P0 SATA_TX_CPU_P0_R SATA_TX_R_P0
net group SENSE: nets VCC_SENSE VCCGT_SENSE VCCSA_SENSE VSS_SENSE VSSGT_SENSE VSSSA_SENSE
net group SIGNAL_V_F_4MIL: nets CPM_RST_R HDD_DEVSLP ITP_PMODE KB_DET# PLT_RST# PLT_RST#_Q PLT_RST#_Q_TPM1 PLT_RST#_Q_TPM2 USB_OC0# USB_OC3# VR_EN
net group SIGNAL_V_F_5MIL: nets 1D2V_VTT_PWRGD 3V_5V_EN ALL_SYS_PWRGD DDR4_DRAMRST# DGPU_HOLD_RST# DGPU_PWR_EN DGPU_PWR_EN_R DGPU_PWROK DGPU_PWROK_R EC_SLP_S0IX# PM_SLP_S0_STG# PM_SLP_S3_STG# SIO_SLP_S3# SYS_PWROK TOUCH_PANEL_INTR#
net group SM_RCOMP: nets SM_RCOMP_0 SM_RCOMP_1 SM_RCOMP_2
net group SMBUS_50-MWS: nets DDC_CLK_PH1 DDC_DATA_PH2 IT8010_WRST# UIM_DATA UIM_DATA_R
net group SPI-MW: nets EC_SPI_CS0#_R PCH_SPI_CS2# SIO_EXT_SCI# SIO_RCIN# SPI1_HOLD_ROM_R SPI1_WP_ROM_R SPI3_CLK_ROM SPI3_CLK_ROM_R SPI3_HOLD_ROM_R SPI3_SI_ROM SPI3_SI_ROM_R SPI3_SO_ROM SPI3_SO_ROM_R SPI3_WP_ROM_R SPI_CS2#_R SPI_CS2#_R_TPM1 SPI_CS2#_R_TPM2 SPI_CS_CPU_N1 SPI_CS_ROM_N1 SPI_HOLD_CPU SPI_HOLD_ROM SPI_HOLD_ROM_R SPI_IRQ#_TPM1 SPI_IRQ#_TPM2
net group T8-MW: nets CMP_VOUT0
net group TESTPD_4MIL: nets CPU_A16_TP CPU_D1_TP CPU_D3_TP CPU_D4_TP CPU_D5_TP CPU_D6_TP RSVD_TP_AK12 RSVD_TP_AK13 RSVD_TP_AW70 RSVD_TP_AW71 RSVD_TP_BA68 RSVD_TP_BA70 RSVD_TP_BB68 RSVD_TP_BB69 TP1_AY4 TP2_BB3 TP4_BB5 TP5_AU5 TP6_AT5
net group THERM_10M-MS: nets FON#
net group THERM_SHUTDOWN: nets GPU_PWR_LEVEL GPU_PWR_LEVEL_R GPU_T_CRIT# GPU_T_CRIT_R# PURE_HW_SHUTDOWN# T_CRIT# THERM_SYS_SHDN#
net group UART_MW-MW: nets LPSS_UART2_CTS# LPSS_UART2_RXD LPSS_UART2_TXD UART0_CTS# UART0_RTS# UART0_TXD UART1_CTS# UART1_RTS# UART1_RXD
net group UIM_CLK: nets UIM_CLK UIM_CLK_C UIM_CLK_R
net group USB30_RX_CPU_N2: nets USB3_RXN3_R
net group USB30_RX_CPU_P2: nets USB3_RXP3_R
net group USB30_TX_CPU_N1: nets USB3_PTX_CRX_N1_R
net group USB30_TX_CPU_P1: nets USB3_PTX_CRX_P1_R
net group USB_CAMERA_PN4: nets USB_CAMERA_PN4
net group USB_CAMERA_PP4: nets USB_CAMERA_PP4
net group USB_CPU_PN1: nets USB_PN1_C
net group USB_CPU_PP1: nets USB_PP1_C
net group USB_WWAN_N_R: nets USB_WWAN_N_R
net group USB_WWAN_PP8: nets USB_WWAN_P_R
net group VRAM_CMD_ODT: nets CASA0# CASA1# CKEA0 CKEA1 ODTA0 ODTA1 RASA0# RASA1# WEA0# WEA1#
net group VRAM_DQA-MWS: nets DQA0_0 DQA0_1 DQA0_2 DQA0_3 DQA0_4 DQA0_5 DQA0_6 DQA0_7 DQA0_8 DQA0_9 DQA0_10 DQA0_11 DQA0_12 DQA0_13 DQA0_14 DQA0_15 DQA0_16 DQA0_17 DQA0_18 DQA0_19 DQA0_20 DQA0_21 DQA0_22 DQA0_23 DQA0_24 DQA0_25 DQA0_26 DQA0_27 DQA0_28 DQA0_29 DQA0_30 DQA0_31 DQA1_0 DQA1_1 DQA1_2 DQA1_3 DQA1_4 DQA1_5 DQA1_6 DQA1_7 DQA1_8 DQA1_9 DQA1_10 DQA1_11 DQA1_12 DQA1_13 DQA1_14 DQA1_15 DQA1_16 DQA1_17 DQA1_18 DQA1_19 DQA1_20 DQA1_21 DQA1_22 DQA1_23 DQA1_24 DQA1_25 DQA1_26 DQA1_27 DQA1_28 DQA1_29 DQA1_30 DQA1_31
net group VRAM_DQMA: nets DQMA0 DQMA1 DQMA2 DQMA3 DQMA4 DQMA5 DQMA6 DQMA7
net group VRAM_MAA: nets MAA0 MAA1 MAA2 MAA3 MAA4 MAA5 MAA6 MAA7 MAA8 MAA9 MAA10 MAA11 MAA12 MAA13 MAA14 MAA15 MAA_BA0 MAA_BA1 MAA_BA2
net group XDP-MW: nets BP_PWRGD_RST# SPI0_MOSI_XDP SPI0_MOSI_XDP_R XDP_DBRESET_XDP# XDP_PRDY# XDP_PREQ# XDP_PRSNT_PIN1 XDP_SPI0_IO2 XDP_TDI XDP_TDO_CPU XDP_TMS XDP_TRST#
net group XDP_BPM-MW: nets XDP_BPM0 XDP_BPM1 XDP_BPM2 XDP_BPM3
net group XDP_TCLK-MWS: nets XDP_TCK_JTAGX XDP_TCLK XDP_TCLK1
net group XTAL24: nets XTAL24_OUT
net group XTAL-MW: nets LANXIN LANXOUT RTC_X1 RTC_X2 XTAL1 XTAL2 XTAL_KBC_2 XTL_27M_X1_VGA XTL_27M_X2_VGA

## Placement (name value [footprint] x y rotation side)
AFTP2501  AFTE14P-GP  [AFTE14P-75]  186.94 9.64 0 top
AFTP2502  AFTE14P-GP  [AFTE14P-75]  230.12 41.9 90 top
AFTP2801  AFTE14P-GP  [AFTE14P-75]  211.79 48.45 180 top
AFTP2802  AFTE14P-GP  [AFTE14P-75]  214.63 52.06 0 top
AFTP2803  AFTE14P-GP  [AFTE14P-75]  214.12 69.28 0 top
AFTP2901  AFTE14P-GP  [AFTE14P-75]  37.08 12.23 0 top
AFTP2902  AFTE14P-GP  [AFTE14P-75]  37.06 10.3 0 top
AFTP2903  AFTE14P-GP  [AFTE14P-75]  35.36 14.01 0 top
AFTP2904  AFTE14P-GP  [AFTE14P-75]  32.84 17.23 270 top
AFTP4301  AFTE14P-GP  [AFTE14P-75]  55.02 105.37 180 top
AFTP4302  AFTE14P-GP  [AFTE14P-75]  53.09 105.29 180 top
AFTP4303  AFTE14P-GP  [AFTE14P-75]  55.37 119.49 180 top
AFTP4304  AFTE14P-GP  [AFTE14P-75]  33.15 71.23 0 top
AFTP4305  AFTE14P-GP  [AFTE14P-75]  57.4 119.49 180 top
AFTP4306  AFTE14P-GP  [AFTE14P-75]  53.34 119.49 180 top
AFTP4307  AFTE14P-GP  [AFTE14P-75]  220.22 12.81 0 top
AFTP4308  AFTE14P-GP  [AFTE14P-75]  221.92 11.92 0 top
AFTP4309  AFTE14P-GP  [AFTE14P-75]  198.75 40.88 0 top
AFTP4310  AFTE14P-GP  [AFTE14P-75]  238.63 33.77 0 top
AFTP4311  AFTE14P-GP  [AFTE14P-75]  236.73 33.89 0 top
AFTP4312  AFTE14P-GP  [AFTE14P-75]  234.82 33.89 0 top
AFTP4313  AFTE14P-GP  [AFTE14P-75]  227.46 29.96 0 top
AFTP4314  AFTE14P-GP  [AFTE14P-75]  229.11 33.13 0 top
AFTP4315  AFTE14P-GP  [AFTE14P-75]  229.11 31.1 0 top
AFTP4316  AFTE14P-GP  [AFTE14P-75]  50.22 102.52 0 top
AFTP5601  AFTE14P-GP  [AFTE14P-75]  261.87 21.07 0 top
AFTP5801  AFTE14P-GP  [AFTE14P-75]  44.96 64.09 0 top
AFTP5802  AFTE14P-GP  [AFTE14P-75]  32.89 56.5 0 top
AFTP5803  AFTE14P-GP  [AFTE14P-75]  38.99 54.09 270 top
AFTP5804  AFTE14P-GP  [AFTE14P-75]  40.26 55.99 270 top
AFTP5805  AFTE14P-GP  [AFTE14P-75]  38.61 57.52 270 top
AFTP5806  AFTE14P-GP  [AFTE14P-75]  37.52 68.26 0 top
AFTP5807  AFTE14P-GP  [AFTE14P-75]  35.69 67.7 0 top
AFTP6101  AFTE14P-GP  [AFTE14P-75]  267.33 30.34 0 top
AFTP6102  AFTE14P-GP  [AFTE14P-75]  283.97 46.98 0 top
AFTP6105  AFTE14P-GP  [AFTE14P-75]  267.21 36.82 180 top
AFTP6201  AFTE14P-GP  [AFTE14P-75]  188.93 44.59 0 top
AFTP6202  AFTE14P-GP  [AFTE14P-75]  179.58 23.73 0 top
AFTP6203  AFTE14P-GP  [AFTE14P-75]  179.58 37.2 0 top
AFTP6204  AFTE14P-GP  [AFTE14P-75]  92.99 115.83 0 top
AFTP6206  AFTE14P-GP  [AFTE14P-75]  179.58 33.39 0 top
AFTP6207  AFTE14P-GP  [AFTE14P-75]  175.77 33.64 0 top
AFTP6208  AFTE14P-GP  [AFTE14P-75]  175.77 31.74 0 top
AFTP6209  AFTE14P-GP  [AFTE14P-75]  93.04 113.93 0 top
AFTP6213  AFTE14P-GP  [AFTE14P-75]  175.77 29.83 0 top
AFTP6214  AFTE14P-GP  [AFTE14P-75]  175.77 25.77 0 top
AFTP6215  AFTE14P-GP  [AFTE14P-75]  179.58 29.58 0 top
AFTP6216  AFTE14P-GP  [AFTE14P-75]  177.67 37.32 0 top
AFTP6217  AFTE14P-GP  [AFTE14P-75]  19.99 51.17 0 top
AFTP6218  AFTE14P-GP  [AFTE14P-75]  179.58 25.64 0 top
AFTP6219  AFTE14P-GP  [AFTE14P-75]  175.77 37.45 0 top
AFTP6220  AFTE14P-GP  [AFTE14P-75]  179.58 39.1 0 top
AFTP6221  AFTE14P-GP  [AFTE14P-75]  177.67 23.73 0 top
AFTP6222  AFTE14P-GP  [AFTE14P-75]  175.77 23.86 0 top
AFTP6223  AFTE14P-GP  [AFTE14P-75]  179.58 31.48 0 top
AFTP6224  AFTE14P-GP  [AFTE14P-75]  177.67 29.7 0 top
AFTP6225  AFTE14P-GP  [AFTE14P-75]  177.67 35.42 0 top
AFTP6226  AFTE14P-GP  [AFTE14P-75]  177.67 33.51 0 top
AFTP6227  AFTE14P-GP  [AFTE14P-75]  179.58 27.67 0 top
AFTP6228  AFTE14P-GP  [AFTE14P-75]  175.77 27.93 0 top
AFTP6229  AFTE14P-GP  [AFTE14P-75]  175.77 35.55 0 top
AFTP6230  AFTE14P-GP  [AFTE14P-75]  177.67 25.64 0 top
AFTP6231  AFTE14P-GP  [AFTE14P-75]  177.67 31.61 0 top
AFTP6232  AFTE14P-GP  [AFTE14P-75]  177.67 39.23 0 top
AFTP6233  AFTE14P-GP  [AFTE14P-75]  179.58 35.29 0 top
AFTP6234  AFTE14P-GP  [AFTE14P-75]  177.67 27.8 0 top
AFTP6235  AFTE14P-GP  [AFTE14P-75]  186.94 5.95 0 top
AFTP6236  AFTE14P-GP  [AFTE14P-75]  138.94 5.45 90 top
AFTP6237  AFTE14P-GP  [AFTE14P-75]  139.06 9.26 90 top
AFTP6238  AFTE14P-GP  [AFTE14P-75]  140.84 5.45 90 top
AFTP6239  AFTE14P-GP  [AFTE14P-75]  169.54 9.64 0 top
AFTP6240  AFTE14P-GP  [AFTE14P-75]  140.97 9.26 90 top
AFTP6241  AFTE14P-GP  [AFTE14P-75]  139.06 7.35 90 top
AFTP6242  AFTE14P-GP  [AFTE14P-75]  140.97 7.35 90 top
AFTP6243  AFTE14P-GP  [AFTE14P-75]  180.64 43.85 0 top
AFTP6244  AFTE14P-GP  [AFTE14P-75]  17.27 21.96 0 top
AFTP6245  AFTE14P-GP  [AFTE14P-75]  190.88 44.56 90 top
AFTP6246  AFTE14P-GP  [AFTE14P-75]  183.72 53.35 90 top
AFTP6247  AFTE14P-GP  [AFTE14P-75]  185.65 53.76 90 top
AFTP6248  AFTE14P-GP  [AFTE14P-75]  185.67 46.72 90 top
AFTP6249  AFTE14P-GP  [AFTE14P-75]  91.39 118.86 0 top
AFTP6252  AFTE14P-GP  [AFTE14P-75]  93.68 104.92 0 top
AFTP6253  AFTE14P-GP  [AFTE14P-75]  100.46 121.78 0 top
AFTP6254  AFTE14P-GP  [AFTE14P-75]  103.12 106.03 0 top
AFTP6255  AFTE14P-GP  [AFTE14P-75]  93.09 123.05 0 top
AFTP6256  AFTE14P-GP  [AFTE14P-75]  93.82 106.8 0 top
AFTP6257  AFTE14P-GP  [AFTE14P-75]  92.96 117.74 0 top
AFTP6258  AFTE14P-GP  [AFTE14P-75]  103.23 109.46 0 top
AFTP6259  AFTE14P-GP  [AFTE14P-75]  90.14 98.74 0 top
AFTP6260  AFTE14P-GP  [AFTE14P-75]  95.25 120 0 top
AFTP6266  AFTE14P-GP  [AFTE14P-75]  91.97 107.27 0 top
AFTP6301  AFTE14P-GP  [AFTE14P-75]  285.27 38.85 270 top
AFTP6302  AFTE14P-GP  [AFTE14P-75]  283.41 38.26 270 top
AFTP6303  AFTE14P-GP  [AFTE14P-75]  282.91 35.8 270 top
AFTP6304  AFTE14P-GP  [AFTE14P-75]  284.58 36.69 270 top
AFTP6307  AFTE14P-GP  [AFTE14P-75]  220.24 10.96 180 top
AFTP6308  AFTE14P-GP  [AFTE14P-75]  220.24 9.05 180 top
AFTP6309  AFTE14P-GP  [AFTE14P-75]  80.39 110.86 0 top
AFTP6310  AFTE14P-GP  [AFTE14P-75]  85.01 110.83 0 top
AFTP6311  AFTE14P-GP  [AFTE14P-75]  278.64 26.91 270 top
AFTP6312  AFTE14P-GP  [AFTE14P-75]  76.33 110.98 0 top
AFTP6313  AFTE14P-GP  [AFTE14P-75]  82.55 110.86 0 top
AFTP6314  AFTE14P-GP  [AFTE14P-75]  242.87 26.38 180 top
AFTP6315  AFTE14P-GP  [AFTE14P-75]  83.82 109.33 0 top
AFTP6317  AFTE14P-GP  [AFTE14P-75]  91.19 124.45 0 top
AFTP6318  AFTE14P-GP  [AFTE14P-75]  72.39 113.9 0 top
AFTP7001  AFTE14P-GP  [AFTE14P-75]  209.42 47.36 180 top
AFTP8902  AFTE14P-GP  [AFTE14P-75]  277.75 25 0 top
AFTP8903  AFTE14P-GP  [AFTE14P-75]  271.25 21.3 90 top
AFTP8904  AFTE14P-GP  [AFTE14P-75]  269.42 20.71 90 top
BATT1  ACES-CON10-46-GP-U  [50299-01001-002-U]  234.9 22 180 bottom
C715  SC10U6D3V3MX-GP  [C603H38]  102.59 65.92 270 top
C716  SC1U10V2KX-1GP  [C402H22]  127.89 94.85 270 bottom
C717  SC1U10V2KX-1GP  [C402H22]  88.77 92.06 0 bottom
C718  SCD1U16V2KX-3GP  [C402H22]  150.98 11.24 0 top
C719  SC1U10V2KX-1GP  [C402H22]  145.03 11.06 0 top
C720  SCD1U16V2KX-3GP  [C402H22]  118.99 80.93 0 top
C721  SCD1U16V2KX-3GP  [C402H22]  119.81 80.88 0 top
C722  SC1U10V2KX-1GP  [C402H22]  101.45 70.88 270 top
C1101  SC1U10V2KX-1GP  [C402H22]  105.54 85.2 270 top
C1102  SC1U10V2KX-1GP  [C402H22]  112.52 87.36 180 top
C1103  SC1U10V2KX-1GP  [C402H22]  105.66 87.87 270 top
C1113  SC22U6D3V3MX-1-GP  [C603H40]  123.06 77.07 270 top
C1116  SC1U10V2KX-1GP  [C402H22]  105.66 87.06 270 top
C1117  SC1U10V2KX-1GP  [C402H22]  106.3 86.22 270 top
C1122  SC22U6D3V3MX-1-GP  [C603H40]  157.61 62.82 270 bottom
C1123  SC10U6D3V3MX-GP  [C603H38]  123.34 74.99 270 top
C1136  SC1U10V2KX-1GP  [C402H22]  97.66 79.61 0 top
C1138  SC1U10V2KX-1GP  [C402H22]  98.55 79.61 0 top
C1147  SC1U10V2KX-1GP  [C402H22]  106.1 106.54 180 top
C1148  SC1U10V2KX-1GP  [C402H22]  106.91 106.54 180 top
C1149  SC1U10V2KX-1GP  [C402H22]  102.62 82.03 90 top
C1150  SC1U10V2KX-1GP  [C402H22]  90.04 83.7 270 top
C1151  SC1U10V2KX-1GP  [C402H22]  105.87 70.8 270 top
C1152  SC1U10V2KX-1GP  [C402H22]  111.4 70.57 0 top
C1153  SC1U10V2KX-1GP  [C402H22]  113.92 74.03 180 top
C1154  SC1U10V2KX-1GP  [C402H22]  114.81 74.03 180 top
C1172  SC1U10V2KX-1GP  [C402H22]  144.2 84.39 0 top
C1173  SC1U10V2KX-1GP  [C402H22]  120.69 78.72 0 top
C1174  SC1U10V2KX-1GP  [C402H22]  124.9 78.21 0 top
C1175  SC1U10V2KX-1GP  [C402H22]  143.64 81.39 180 bottom
C1176  SC10U6D3V3MX-GP  [C603H38]  145.03 80.76 180 bottom
C1180  SC1U10V2KX-1GP  [C402H22]  121.51 78.72 0 top
C1181  SC22U6D3V3MX-1-GP  [C603H40]  145.8 86.01 270 top
C1182  SC22U6D3V5MX-2GP  [C805H58]  154.79 83.4 270 bottom
C1183  SC10U6D3V3MX-GP  [C603H38]  145.03 70.6 180 bottom
C1202  SC10U6D3V3MX-GP  [C603H38]  165.48 18.91 90 top
C1203  SC10U6D3V3MX-GP  [C603H38]  155.32 11.03 0 top
C1204  SC10U6D3V3MX-GP  [C603H38]  160.27 11.29 0 top
C1205  SC10U6D3V3MX-GP  [C603H38]  161.93 11.29 0 top
C1206  SC10U6D3V3MX-GP  [C603H38]  149.35 11.42 0 top
C1207  SC1U10V2KX-1GP  [C402H22]  179.6 20.1 270 top
C1208  SC10U6D3V3MX-GP  [C603H38]  115.7 22.59 0 top
C1209  SC10U6D3V3MX-GP  [C603H38]  164.97 11.03 0 top
C1210  SC10U6D3V3MX-GP  [C603H38]  167.89 11.16 0 top
C1211  SC4D7U6D3V2MX-1-GP  [C402H22]  113.54 20.19 90 top
C1212  SC4D7U6D3V2MX-1-GP  [C402H22]  113.54 19.3 90 top
C1213  SC1U10V2KX-L1-GP  [C402H22]  179.6 20.99 270 top
C1214  SC1U10V2KX-1GP  [C402H22]  172.72 19.16 0 top
C1215  SC1U10V2KX-1GP  [C402H22]  147.19 19.29 0 top
C1216  SC1U10V2KX-1GP  [C402H22]  120.02 11.03 0 top
C1217  SC1U10V2KX-1GP  [C402H22]  134.62 11.17 0 top
C1218  SC1U10V2KX-1GP  [C402H22]  96.27 18.03 0 top
C1219  SC1U10V2KX-1GP  [C402H22]  100.59 11.3 0 top
C1221  SC1U10V2KX-1GP  [C402H22]  58.04 11.42 0 top
C1222  SCD022U16V2KX-3GP  [C402H22]  87.53 9.05 270 bottom
C1223  SC4D7U6D3V2MX-1-GP  [C402H22]  187.45 7.3 270 bottom
C1224  SC4D7U6D3V2MX-1-GP  [C402H22]  187.45 9.03 270 bottom
C1225  SC1U10V2KX-1GP  [C402H22]  115.57 14.34 90 top
C1226  SC1U10V2KX-1GP  [C402H22]  115.57 13.45 90 top
C1227  SC4D7U6D3V2MX-1-GP  [C402H22]  187.45 6.44 270 bottom
C1228  SCD1U16V2KX-L-GP  [C402H22]  113.92 17.64 180 top
C1229  SCD1U16V2KX-3GP  [C402H22]  86.36 13.19 180 top
C1230  SC4D7U6D3V2MX-1-GP  [C402H22]  115.57 11.67 90 top
C1231  SC4D7U6D3V2MX-1-GP  [C402H22]  112.14 18.53 0 top
C1232  SC4D7U6D3V2MX-1-GP  [C402H22]  111.25 18.53 0 top
C1301  SCD1U16V2KX-3GP  [C402H22]  83.57 54.85 180 bottom
C1303  SC10U6D3V3MX-GP  [C603H38]  56.01 25.26 180 top
C1304  SC10U6D3V3MX-GP  [C603H38]  79.38 11.29 0 top
C1305  SC10U6D3V3MX-GP  [C603H38]  156.97 11.16 0 top
C1306  SC10U6D3V3MX-GP  [C603H38]  124.85 11.55 0 top
C1307  SC10U6D3V3MX-GP  [C603H38]  174.62 20.43 90 top
C1308  SC10U6D3V3MX-GP  [C603H38]  63.75 11.67 0 top
C1309  SC10U6D3V3MX-GP  [C603H38]  50.93 11.67 0 top
C1310  SC10U6D3V3MX-GP  [C603H38]  104.27 19.54 0 top
C1311  SC4D7U6D3V2MX-1-GP  [C402H22]  178.33 19.72 180 top
C1312  SC4D7U6D3V2MX-1-GP  [C402H22]  176.56 19.72 180 top
C1313  SC1U10V2KX-1GP  [C402H22]  177.44 19.72 180 top
C1314  SC1U10V2KX-L1-GP  [C402H22]  179.6 21.88 270 top
C1315  SC1U10V2KX-1GP  [C402H22]  110.36 67.04 180 top
C1316  SC1U10V2KX-1GP  [C402H22]  65.79 28.18 180 top
C1317  SC1U10V2KX-1GP  [C402H22]  97.16 64.96 270 top
C1318  SC1U10V2KX-1GP  [C402H22]  98.68 65.52 180 top
C1319  SC1U10V2KX-1GP  [C402H22]  110.85 54.35 270 bottom
C1320  SC1U10V2KX-1GP  [C402H22]  122.43 19.16 0 top
C1321  SC1U10V2KX-1GP  [C402H22]  100.46 65.52 180 top
C1322  SC1U10V2KX-1GP  [C402H22]  113.41 65.52 180 top
C1323  SCD022U16V2KX-3GP  [C402H22]  87.5 56.25 180 bottom
C1324  SC10U6D3V3MX-GP  [C603H38]  185.95 5.93 180 bottom
C1325  SC10U6D3V3MX-GP  [C603H38]  115.57 15.48 90 top
C1326  SC1U10V2KX-1GP  [C402H22]  115.57 12.56 90 top
C1327  SC1U10V2KX-1GP  [C402H22]  187.45 8.16 270 bottom
C1328  SCD1U16V2KX-L-GP  [C402H22]  113.03 17.64 180 top
C1329  SC2D2U10V3KX-L-GP  [C603H36]  115.04 17.49 180 top
C1330  SC4D7U6D3V2MX-1-GP  [C402H22]  113.54 21.97 90 top
C1331  SC4D7U6D3V2MX-1-GP  [C402H22]  113.54 21.08 90 top
C1601  SCD1U16V2KX-3GP  [C402H22]  117.98 90.79 270 bottom
C1602  SCD1U16V2KX-3GP  [C402H22]  117.98 89.9 270 bottom
C1603  SCD1U16V2KX-3GP  [C402H22]  120.78 91.04 270 bottom
C1604  SCD1U16V2KX-3GP  [C402H22]  120.78 91.93 270 bottom
C1605  SCD22U10V2KX-1GP  [C402H22]  123.65 96.89 180 bottom
C1606  SCD22U10V2KX-1GP  [C402H22]  124.54 96.89 180 bottom
C1607  SCD22U10V2KX-1GP  [C402H22]  125.15 94.41 180 bottom
C1608  SCD22U10V2KX-1GP  [C402H22]  126 94.42 180 bottom
C1609  SCD22U10V2KX-1GP  [C402H22]  122.56 94.42 180 bottom
C1610  SCD22U10V2KX-1GP  [C402H22]  121.72 94.42 180 bottom
C1611  SCD22U10V2KX-1GP  [C402H22]  118.87 94.35 180 bottom
C1612  SCD22U10V2KX-1GP  [C402H22]  117.98 94.35 180 bottom
C1701  SC220P50V2KX-3GP  [C402H22]  154.56 74.79 180 bottom
C1704  SC10U6D3V3MX-GP  [C603H38]  154.89 81.85 270 bottom
C1801  SC15P50V2JN-2-GP  [C402H22]  112.83 94.88 270 bottom
C1802  SC15P50V2JN-2-GP  [C402H22]  114.58 94.88 90 bottom
C1803  SC6D8P50V2DN-GP  [C402H22]  135.13 55.89 180 bottom
C1804  SC6D8P50V2DN-GP  [C402H22]  135.13 57.64 0 bottom
C1805  SC1U10V2KX-1GP  [C402H22]  137.82 47.61 270 bottom
C1806  SC1U10V2KX-1GP  [C402H22]  134.24 47.86 0 top
C2101  SC1U10V2KX-1GP  [C402H22]  120.78 76.57 90 top
C2102  SC1U10V2KX-1GP  [C402H22]  115.95 75.55 270 top
C2103  SC1U10V2KX-1GP  [C402H22]  131.78 70.52 0 top
C2104  SC1U10V2KX-1GP  [C402H22]  108.71 91.04 270 bottom
C2105  SC1U10V2KX-1GP  [C402H22]  119.38 75.17 90 top
C2106  SC1U10V2KX-1GP  [C402H22]  123.24 72.12 270 top
C2107  SC1U10V2KX-1GP  [C402H22]  123.24 73.01 270 top
C2108  SC1U10V2KX-1GP  [C402H22]  157.76 61.73 270 bottom
C2109  SC1U10V2KX-1GP  [C402H22]  123.09 76.03 270 top
C2110  SCD1U16V2KX-3GP  [C402H22]  123.14 78.17 270 top
C2111  SCD1U16V2KX-3GP  [C402H22]  123.24 73.85 270 top
C2112  SCD1U16V2KX-3GP  [C402H22]  125.91 64.93 90 top
C2113  SC22U6D3V3MX-1-GP  [C603H40]  115.95 82.15 270 top
C2114  SC22U6D3V3MX-1-GP  [C603H40]  116.84 77.58 270 top
C2115  SC22U6D3V3MX-1-GP  [C603H40]  116.46 79.61 0 top
C2116  SC1U10V2KX-1GP  [C402H22]  125.73 91.3 0 bottom
C2117  SC1U10V2KX-1GP  [C402H22]  126.24 52.69 0 top
C2118  SCD1U16V2KX-3GP  [C402H22]  127.13 52.69 0 top
C2119  SCD1U16V2KX-3GP  [C402H22]  128.02 52.69 0 top
C2120  SC1U10V2KX-1GP  [C402H22]  115.95 76.44 270 top
C2121  SC1U10V2KX-1GP  [C402H22]  121.03 74.15 180 top
C2122  SC22U6D3V3MX-1-GP  [C603H40]  122.3 85.33 180 top
C2123  SC22U6D3V3MX-1-GP  [C603H40]  148.34 81.42 0 top
C2124  SC1U10V2KX-1GP  [C402H22]  145.01 88.45 90 top
C2401  SC10U6D3V3MX-GP  [C603H38]  207.77 42.28 180 top
C2402  SC220P50V2KX-3GP  [C402H22]  205.36 40.63 0 top
C2403  SC47P50V2JN-3GP  [C402H22]  203.71 25.77 90 bottom
C2405  SC100P50V2JN-3GP  [C402H22]  200.15 24.5 0 bottom
C2406  SCD1U16V2KX-3GP  [C402H22]  200.28 22.34 180 bottom
C2407  SCD1U16V2KX-3GP  [C402H22]  203.71 17.51 270 top
C2408  SCD1U16V2KX-3GP  [C402H22]  201.22 13.78 180 top
C2410  SCD1U16V2KX-3GP  [C402H22]  209.93 40.5 270 top
C2411  SCD1U16V2KX-3GP  [C402H22]  200.79 19.42 270 top
C2412  SCD1U16V2KX-3GP  [C402H22]  202.59 35.55 270 bottom
C2413  SCD1U16V2KX-3GP  [C402H22]  201.55 22.08 90 bottom
C2414  SCD1U16V2KX-3GP  [C402H22]  218.82 27.98 90 top
C2415  SC2D2U10V3KX-1GP  [C603H36]  203.71 12.94 90 top
C2416  SCD1U16V2KX-3GP  [C402H22]  203.66 14.03 90 top
C2417  SC2D2U10V3KX-1GP  [C603H36]  209.68 41.64 270 top
C2418  SC1U10V2KX-1GP  [C402H22]  218.92 27.52 180 bottom
C2420  SCD1U16V2KX-3GP  [C402H22]  218.57 24.12 0 top
C2421  SCD1U16V2KX-3GP  [C402H22]  203.66 14.92 90 top
C2422  SCD1U16V2KX-3GP  [C402H22]  210.16 18.96 0 top
C2423  SCD1U16V2KX-3GP  [C402H22]  209.55 43.32 270 bottom
C2424  SC10P50V2JN-4GP  [C402H22]  209.8 14.84 270 top
C2425  SC10P50V2JN-4GP  [C402H22]  206.25 14.84 90 top
C2426  SC1U10V2KX-1GP  [C402H22]  216.79 19.04 0 top
C2427  SC2200P50V2KX-2GP  [C402H22]  205.49 17.51 270 top
C2428  SCD1U16V2KX-3GP  [C402H22]  219.58 14.72 0 top
C2429  SCD1U16V2KX-3GP  [C402H22]  217.93 34.4 0 bottom
C2435  SC2200P50V2KX-2GP  [C402H22]  207.39 18.78 0 top
C2441  SC2200P50V2KX-2GP  [C402H22]  200.38 9.56 180 bottom
C2501  SC10U6D3V3MX-GP  [C603H38]  147.04 48.63 180 top
C2502  SCD1U16V2KX-3GP  [C402H22]  145.67 48.04 180 top
C2503  SCD22U10V2KX-1GP  [C402H22]  224.59 39.71 180 top
C2504  SCD1U16V2KX-3GP  [C402H22]  160.53 53.45 90 bottom
C2505  SC10U6D3V3MX-GP  [C603H38]  158.78 52.46 0 bottom
C2506  SC10U6D3V3MX-GP  [C603H38]  103.5 8.62 90 top
C2507  SCD1U16V2KX-3GP  [C402H22]  102.62 9.89 90 top
C2601  SC10U6D3V3MX-GP  [C603H38]  79.86 97.22 0 bottom
C2602  SCD1U16V2KX-3GP  [C402H22]  78.46 97.65 0 bottom
C2604  SC4D7U6D3V3KX-GP  [C603H36]  213.61 48.25 90 top
C2605  SCD1U16V2KX-3GP  [C402H22]  209.32 53.66 90 bottom
C2606  SC470P50V2KX-3GP  [C402H22]  194.89 31.23 90 bottom
C2607  SC2200P50V2KX-2GP  [C402H22]  78.46 95.95 180 bottom
C2608  SCD1U16V2KX-3GP  [C402H22]  70.51 97.65 90 bottom
C2609  SCD1U16V2KX-3GP  [C402H22]  70.51 96.84 90 bottom
C2610  SCD1U16V2KX-3GP  [C402H22]  70.51 86.4 90 bottom
C2611  SC4D7U6D3V3KX-GP  [C603H36]  209.6 52.54 90 bottom
C2619  SCD1U16V2KX-3GP  [C402H22]  203.71 112.63 270 bottom
C2620  SCD1U16V2KX-3GP  [C402H22]  201.93 112.63 90 bottom
C2621  SC10U6D3V3MX-GP  [C603H38]  207.04 105.65 270 bottom
C2622  SCD1U16V2KX-3GP  [C402H22]  206.71 106.79 270 bottom
C2623  SC2200P50V2KX-2GP  [C402H22]  203.76 103.67 90 bottom
C2701  SC4D7U6D3V3KX-GP  [C603H36]  27.69 4.31 0 top
C2702  SC4D7U6D3V3KX-GP  [C603H36]  21.56 5.61 180 top
C2703  SC1U10V2KX-1GP  [C402H22]  27.44 5.96 90 top
C2704  SC1U10V2KX-1GP  [C402H22]  25.4 10.02 180 bottom
C2705  SC2D2U10V3KX-1GP  [C603H36]  22.84 4.77 180 top
C2706  SC10U6D3V3MX-GP  [C603H38]  34.67 8.49 0 top
C2707  SCD1U16V2KX-3GP  [C402H22]  33.53 8.62 0 top
C2708  SC10U6D3V3MX-GP  [C603H38]  28.45 17.64 270 top
C2709  SCD1U16V2KX-3GP  [C402H22]  28.83 16.5 270 top
C2710  SCD1U16V2KX-3GP  [C402H22]  19.56 5.7 0 top
C2711  SC4D7U6D3V3KX-GP  [C603H36]  18.41 5.32 0 top
C2712  SC10U6D3V3MX-GP  [C603H38]  29.06 7.61 180 top
C2713  SC10U6D3V3MX-GP  [C603H38]  17.78 9.84 270 top
C2714  SCD1U16V2KX-3GP  [C402H22]  28.83 4.57 0 top
C2715  SC4D7U6D3V3KX-GP  [C603H36]  30.33 7.61 0 top
C2716  SC4D7U6D3V3KX-GP  [C603H36]  24 14.84 180 bottom
C2717  SCD1U16V2KX-3GP  [C402H22]  25.15 14.72 180 bottom
C2718  SC4D7U6D3V3KX-GP  [C603H36]  23.11 18.65 180 top
C2719  SCD1U16V2KX-3GP  [C402H22]  22.86 14.72 180 bottom
C2720  SCD1U16V2KX-3GP  [C402H22]  19.18 14.95 270 bottom
C2721  SCD1U16V2KX-3GP  [C402H22]  31.47 7.87 0 top
C2722  SCD22U10V2KX-1GP  [C402H22]  43.33 4.62 0 bottom
C2724  SCD1U16V2KX-3GP  [C402H22]  44.19 4.67 0 bottom
C2725  SCD1U16V2KX-3GP  [C402H22]  36.38 3.04 270 bottom
C2907  SC10U6D3V3MX-GP  [C603H38]  18.01 7.28 270 top
C2908  SC10U6D3V3MX-GP  [C603H38]  18.01 8.55 270 top
C3101  SCD1U16V2KX-3GP  [C402H22]  44.96 99.05 180 top
C3102  SCD1U16V2KX-3GP  [C402H22]  42.16 94.6 90 top
C3103  SC4D7U6D3V3KX-GP  [C603H36]  46.15 91.5 0 top
C3104  SCD1U16V2KX-3GP  [C402H22]  48.9 97.14 270 bottom
C3105  SCD1U16V2KX-3GP  [C402H22]  42.16 96.25 90 top
C3106  SCD1U16V2KX-3GP  [C402H22]  46.23 95.44 270 top
C3107  SCD1U16V2KX-3GP  [C402H22]  47.75 92.72 180 bottom
C3108  SCD1U16V2KX-3GP  [C402H22]  48.9 98.03 270 bottom
C3109  SC4D7U6D3V3KX-GP  [C603H36]  39.37 93.08 270 top
C3110  SC15P50V2JN-2-GP  [C402H22]  43.38 90.74 90 bottom
C3111  SCD1U16V2KX-3GP  [C402H22]  45.09 91.17 0 top
C3112  SC15P50V2JN-2-GP  [C402H22]  45.16 90.74 270 bottom
C3113  SCD1U16V2KX-3GP  [C402H22]  44.25 91.17 0 top
C3114  SC1U10V2KX-1GP  [C402H22]  46.23 94.6 270 top
C3115  SCD1U16V2KX-3GP  [C402H22]  41.66 91.93 0 top
C3116  SC4D7U6D3V3KX-GP  [C603H36]  49.81 90.28 270 bottom
C3117  SCD1U16V2KX-3GP  [C402H22]  43.43 93.2 180 top
C3118  SC4D7U6D3V3KX-GP  [C603H36]  46.1 99.05 180 top
C3119  SCD01U50V2KX-1GP  [C402H22]  27.23 97.93 270 bottom
C3120  SCD1U16V2KX-3GP  [C402H22]  51.31 92.7 90 top
C3121  SCD1U16V2KX-3GP  [C402H22]  35.69 95.24 270 top
C3122  SC1U10V2KX-1GP  [C402H22]  36.17 97.14 180 top
C3201  SC56P3KV8JN-1-GP  [C1808H40]  19.53 83.11 0 top
C3401  SC1U10V2KX-1GP  [C402H22]  20.45 61.07 0 bottom
C3402  SCD1U16V2KX-3GP  [C402H22]  27.43 56.63 0 bottom
C3403  SCD1U16V2KX-3GP  [C402H22]  19.56 61.07 0 bottom
C3404  SC22U6D3V3MX-1-GP  [C603H40]  22.86 60.82 0 bottom
C3405  SC22U6D3V3MX-1-GP  [C603H40]  21.59 60.82 0 bottom
C3406  SC10U6D3V3MX-GP  [C603H38]  26.54 58.15 270 bottom
C3504  SCD1U16V2KX-3GP  [C402H22]  274.32 26.27 90 bottom
C3509  SCD1U16V2KX-3GP  [C402H22]  19.05 29.2 0 top
C3511  SC1U10V2KX-1GP  [C402H22]  20.67 34.52 270 bottom
C3514  SC22U6D3V5MX-2GP  [C805H58]  19.81 33.51 180 top
C3515  SC22U6D3V5MX-2GP  [C805H58]  278.13 28.81 90 bottom
C3516  SC1U10V2KX-1GP  [C402H22]  18.16 29.2 0 top
C3517  SCD1U16V2KX-3GP  [C402H22]  278 31.1 90 bottom
C3518  SC1U10V2KX-1GP  [C402H22]  278 30.21 90 bottom
C3519  SC22U6D3V5MX-2GP  [C805H58]  17.91 33.51 180 top
C3601  SCD1U16V2KX-3GP  [C402H22]  23.44 51.72 90 bottom
C3602  SCD1U16V2KX-3GP  [C402H22]  23.44 52.61 90 bottom
C3604  SCD1U16V2KX-3GP  [C402H22]  24.13 25 90 bottom
C3605  SCD1U16V2KX-3GP  [C402H22]  24.13 25.89 90 bottom
C4001  SC470P50V2KX-3GP  [C402H22]  54.33 49.92 0 top
C4002  SC470P50V2KX-3GP  [C402H22]  53.31 49.57 0 top
C4004  SC10U6D3V3MX-GP  [C603H38]  51.94 50.53 0 top
C4005  SC10U25V5KX-GP  [C805H56]  55.7 50.68 0 top
C4007  SCD1U25V2KX-GP  [C402H22]  166.88 60.06 270 bottom
C4009  SC4D7U6D3V3KX-GP  [C603H36]  57.51 48.25 180 top
C4012  SC10U6D3V3MX-GP  [C603H38]  134.85 97.06 0 bottom
C4013  SC10U6D3V3MX-GP  [C603H38]  145.72 90.41 90 bottom
C4014  SCD1U16V2KX-3GP  [C402H22]  154.69 88 180 bottom
C4016  SC10U6D3V3MX-GP  [C603H38]  163.45 58.53 90 bottom
C4033  SC1U10V2KX-1GP  [C402H22]  57.2 54.57 0 top
C4034  SC1U10V2KX-1GP  [C402H22]  149.73 86.04 180 bottom
C4101  SC1U10V2KX-1GP  [C402H22]  144.78 48.04 180 top
C4102  SC1U10V2KX-1GP  [C402H22]  217.3 46.09 180 bottom
C4103  SCD1U16V2KX-3GP  [C402H22]  157.61 51.67 90 top
C5501  SCD1U16V2KX-3GP  [C402H22]  43.69 75.8 180 top
C5502  SC4D7P50V2BN-GP  [C402H22]  55.5 82.03 270 bottom
C5503  SC4D7P50V2BN-GP  [C402H22]  53.72 82.03 90 bottom
C5504  SC4D7P50V2BN-GP  [C402H22]  51.94 81.9 270 bottom
C5505  SC4D7U6D3V3KX-GP  [C603H36]  33.32 83.02 270 top
C5506  SC4D7P50V2BN-GP  [C402H22]  50.16 81.9 90 bottom
C5507  SC4D7P50V2BN-GP  [C402H22]  48.39 81.9 270 bottom
C5508  SCD1U16V2KX-3GP  [C402H22]  52.32 83.17 180 bottom
C5509  SC4D7P50V2BN-GP  [C402H22]  46.61 81.9 90 bottom
C5515  SC1KP50V2KX-1GP  [C402H22]  62.1 76.19 90 top
C5516  SC1KP50V2KX-1GP  [C402H22]  70.97 87.18 0 top
C5531  SCD1U16V2KX-3GP  [C402H22]  55.12 84.19 180 bottom
C5532  SCD1U16V2KX-3GP  [C402H22]  51.44 83.17 180 bottom
C5533  SCD1U16V2KX-3GP  [C402H22]  54.1 84.19 180 bottom
C5534  SCD1U16V2KX-3GP  [C402H22]  47.88 83.17 180 bottom
C5535  SCD1U50V3KX-GP  [C603H36]  61.85 77.33 270 top
C5536  SC1U10V2KX-1GP  [C402H22]  62.99 82.79 90 bottom
C5537  SCD1U16V2KX-3GP  [C402H22]  46.99 83.17 180 bottom
C5538  SCD1U16V2KX-3GP  [C402H22]  62.99 81.9 270 bottom
C5539  SC4D7U6D3V3KX-GP  [C603H36]  43.56 82.71 90 bottom
C5540  SC10P50V2JN-4GP  [C402H22]  41.02 75.42 180 top
C5541  SC10P50V2JN-4GP  [C402H22]  41.91 75.42 180 top
